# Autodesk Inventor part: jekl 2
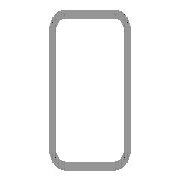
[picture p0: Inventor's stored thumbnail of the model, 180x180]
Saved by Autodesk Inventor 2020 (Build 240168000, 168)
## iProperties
Created: 2019-01
Part Number: jekl 2
Material: Ocel
Description: Duté svařované profily tvářené za studena z nelegované a jemnozrnné konstrukční oceli
Document SubType Name: Modeling
Standard: CSN EN 10219-2
Designer: doma
Standards Organization: CSN
Language: cs-CZ
Size Designation: 80 x 40 x 4  - 2000
Categories: <MemberInstance><Categories><Category DisplayName="Konstrukční profily" InternalName="089c4875-fa83-4c05-b084-43b9cc11f5ed" Mnemonic="GRDR"><CategoryParameter D
Stock Number: 80 x 40 x 4
Density: 7.85 g/cm^3
Appearance: Plech
Mass: 507.043 g
Surface Area: 341.462 cm^2
Volume: 64.5914 cm^3
IsCustomPart: 1
G_L: 2000,000 mm
Author: doma
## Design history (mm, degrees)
node "Počáteční rovina"
node "Koncová rovina"
sketch "Náčrt"
  geometry: L1 (-20, -32)-(-20, 32); L2 (-12, 40)-(12, 40); L3 (20, 32)-(20, -32); L4 (12, -40)-(-12, -40); L5 (-12, 36)-(12, 36); L6 (16, 32)-(16, -32); L7 (12, -36)-(-12, -36); L8 (-16, -32)-(-16, 32); L9 (0, 58.32)-(0, -58.32) reference; L10 (-30.32, 0)-(30.32, 0) reference; A1 r 8 centre (-12, -32) between (-20, -32) and (-12, -40); A2 r 8 centre (-12, 32) between (-12, 40) and (-20, 32); A3 r 8 centre (12, 32) between (20, 32) and (12, 40); A4 r 8 centre (12, -32) between (12, -40) and (20, -32); A5 r 4 centre (-12, 32) between (-12, 36) and (-16, 32); A6 r 4 centre (12, 32) between (16, 32) and (12, 36); A7 r 4 centre (12, -32) between (12, -36) and (16, -32); A8 r 4 centre (-12, -32) between (-16, -32) and (-12, -36)
  constraints: 16 end point, 16 point on circle, 8 centre point, 8 tangent, 4 parallel, 3 equal radius, 2 perpendicular, 7 other
  dimensions: "d7" = 8 radius of A1 (= G_IR); "d10" = 80 distance between parallel lines of L2 L4 (= G_H); "d11" = 40 distance between parallel lines of L1 L3 (= G_W); "d12" = 4 distance between parallel lines of L3 L6 (= G_T); "d15" = 40 distance between parallel lines of L2 L10 (= 0.5 x d10); "d16" = 20 distance between parallel lines of L9 L3 (= 0.5 x d11)
extrude "Těleso" new body sketch "Náčrt" stored distance "d3" = 500; taper "d4" = 0 deg
node "Driven Length"
  sketch "Sketch3"
    geometry: L1 (0, 0)-(10, 0) reference
    constraints: 2 end point, 1 horizontal
  workplane "Work Plane3"
  sketch "Sketch4"
    geometry: L1 (-2, 0)-(12, 0) reference; L2 (-2, 2000)-(12, 2000) reference
    dimensions: "d18" = 2000 distance between parallel lines of L1 L2 (derived)
sketch "Náčrt5"
  geometry: L1 (135.84, -8)-(102.703, 72) reference; L2 (157.053, 126.35)-(864.16, -580.756) reference; L3 (100.485, 69.782)-(807.591, -637.325) reference; L4 (102.703, 72)-(0, 126.35); L5 (0, 126.35)-(-114.223, 54.498); L6 (-114.223, 54.498)-(119.271, -156.924); L7 (119.271, -156.924)-(135.84, -8); L8 (0, 72)-(500, 72) reference; L9 (211.403, 72)-(178.266, -8); L10 (500, -8)-(0, -8) reference; L11 (178.266, -8)-(200.821, -95.703); L12 (200.821, -95.703)-(427.735, -82.462); L13 (276.687, 97.204)-(211.403, 72); L14 (276.687, 97.204)-(547.661, 145.779); L15 (547.661, 145.779)-(617.5, -71.388); L16 (617.5, -71.388)-(427.735, -82.462); 1 further point
  constraints: 22 end point, 4 point on line
extrude "Vysunutí2" cut sketch "Náčrt5" extent not by distance; stored distance "d19" = 0; taper "d20" = 0 deg
chamfer "Zkosení1" distance "d21" = 2; stored, may be unused: second distance "d22" = 2, angle "d23" = 45 deg
body "Solid1"
node "Referenční1"
node "Referenční2"
node "Referenční3"
other parameters: "G_W" = 40 [user parameter; used in 1 equation term], "G_H" = 80 [user parameter; used in 1 equation term], "G_T" = 4 [user parameter; used in 1 equation term], "G_IR" = 8 [user parameter; used in 1 equation term], "G_L" = 2000 (= d18) [user parameter], "G_OFFSET_START" = 0 [user parameter; used in 1 equation term], "G_OFFSET_END" = 0 [user parameter; used in 1 equation term], "d13" = 0 (computed from G_OFFSET_START), "d17" = 90 deg
